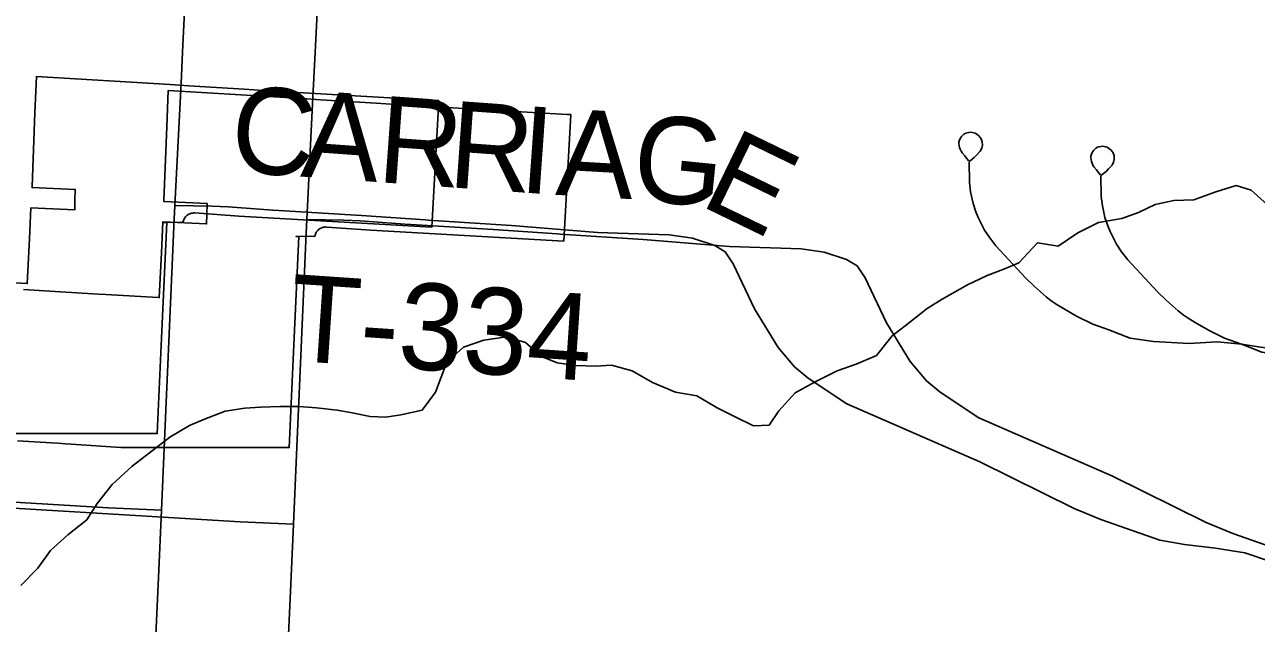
# Model space of a CAD drawing. Extents: x -38.2 to 41.9, y -4 to 24.9.
# Drawn here: x 6.95 to 7.758, y 19.034 to 19.427 of the extents above; entities that cross this region are included whole.
import ezdxf

# ---------------------------------------------------------------- set-up
doc = ezdxf.new("R2010")
doc.units = 0
for name, color, linetype in [('Default', 7, 'Continuous'), ('GM_X_County_Road', 7, 'Continuous'), ('GM_X_Minor_River', 7, 'Continuous'), ('GM_X_State_Location', 7, 'Continuous'), ('GM_X_Township_Road', 7, 'Continuous'), ('GM_X_Township_Road_Text', 7, 'Continuous')]:
    doc.layers.add(name, color=color, linetype=linetype)

msp = doc.modelspace()

# ---------------------------------------------------------------- linework, layer by layer
at = {"layer": 'Default'}
msp.add_lwpolyline([(6.9422, 19.15865), (6.95656, 19.15863), (6.97865, 19.15861), (7.03318, 19.15854), (7.03523, 19.15853), (7.03713, 19.15853), (7.04043, 19.23085), (7.04344, 19.29702), (7.04152, 19.2971), (7.05388, 19.29721), (7.05492, 19.29983), (7.05561, 19.30073), (7.05601, 19.30114), (7.05658, 19.30164), (7.05689, 19.30186), (7.05736, 19.30217), (7.05802, 19.30253), (7.05873, 19.30282), (7.05928, 19.30299), (7.05963, 19.30307), (7.06039, 19.3032), (7.06096, 19.30324), (7.06172, 19.30323), (7.09067, 19.30112), (7.21713, 19.29403), (7.22169, 19.37702), (7.21946, 19.37712), (7.10687, 19.38368), (7.09418, 19.38445), (7.05777, 19.38668), (7.04567, 19.38743), (6.95786, 19.39276), (6.95683, 19.36897), (6.95502, 19.3206), (6.95499, 19.31988), (6.98335, 19.31873), (6.98317, 19.31116), (6.98302, 19.30526), (6.95433, 19.30663), (6.95334, 19.28639), (6.95251, 19.26937), (6.9519, 19.25694), (6.95154, 19.25696), (6.93589, 19.25787)], dxfattribs=at)
at = {"layer": 'GM_X_County_Road'}
for points in [[(7.05271, 19.38845), (7.05397, 19.41352), (7.06396, 19.6125), (7.06434, 19.61953)], [(7.04831, 19.29914), (7.04871, 19.30822), (7.05271, 19.38845)], [(6.94556, 19.15388), (6.96776, 19.15244), (6.97191, 19.15217), (6.97698, 19.15184), (6.98068, 19.1516), (7.01319, 19.14948), (7.02867, 19.14946), (7.04304, 19.14945), (7.06513, 19.14942), (7.11966, 19.14935), (7.12171, 19.14934), (7.12361, 19.14934), (7.1269, 19.22166), (7.12992, 19.28783), (7.128, 19.28791), (7.14036, 19.28802), (7.1414, 19.29064), (7.14209, 19.29154), (7.14249, 19.29195), (7.14306, 19.29245), (7.14336, 19.29267), (7.14384, 19.29299), (7.1445, 19.29334), (7.14521, 19.29363), (7.14576, 19.2938), (7.14611, 19.29389), (7.14687, 19.29401), (7.14744, 19.29405), (7.14819, 19.29404), (7.17715, 19.29193), (7.3036, 19.28484), (7.30816, 19.36783), (7.30594, 19.36793), (7.19334, 19.37449), (7.18066, 19.37526), (7.14424, 19.37749), (7.13215, 19.37824), (7.04434, 19.38357), (7.0433, 19.35978), (7.0415, 19.31141), (7.04147, 19.31069), (7.06983, 19.30954), (7.06965, 19.30197), (7.0695, 19.29607), (7.04081, 19.29745), (7.03982, 19.2772), (7.03899, 19.26018), (7.03838, 19.24775), (7.03802, 19.24777), (7.02236, 19.24869), (7.00335, 19.24979), (6.99859, 19.25007), (6.98448, 19.25092), (6.96659, 19.25199), (6.94954, 19.25302)], [(7.03553, 19.00186), (7.03605, 19.02162), (7.03797, 19.06405), (7.03985, 19.10826), (7.04183, 19.15386), (7.04831, 19.29914)]]:
    msp.add_lwpolyline(points, dxfattribs=at)
at = {"layer": 'GM_X_Minor_River'}
for points in [[(7.76474, 19.30874), (7.75414, 19.31823), (7.7443, 19.32126), (7.73106, 19.31709), (7.71668, 19.31179), (7.70343, 19.31141), (7.69132, 19.30876), (7.68035, 19.30346), (7.66938, 19.29967), (7.65424, 19.29702), (7.64062, 19.2902), (7.62776, 19.28148), (7.61413, 19.28376), (7.60203, 19.27049), (7.59219, 19.26632), (7.58122, 19.26215), (7.56835, 19.25609), (7.5517, 19.24662), (7.54186, 19.24055), (7.52938, 19.2307), (7.51879, 19.22274), (7.50857, 19.20985), (7.49533, 19.20417), (7.48284, 19.19962), (7.46846, 19.19242), (7.45522, 19.18523), (7.44463, 19.17348), (7.4382, 19.164), (7.42798, 19.16362), (7.41549, 19.16969), (7.40413, 19.17538), (7.39088, 19.18335)], [(7.39088, 19.18335), (7.37688, 19.18563), (7.36174, 19.19208), (7.34849, 19.19966), (7.33486, 19.20346), (7.32465, 19.20271), (7.3114, 19.20309), (7.29929, 19.20499), (7.28907, 19.20916), (7.27847, 19.21826), (7.26598, 19.22206), (7.25122, 19.21979), (7.23798, 19.21525), (7.227, 19.20539), (7.21944, 19.18568), (7.21074, 19.17393), (7.19674, 19.1709), (7.1869, 19.16939), (7.17668, 19.16977), (7.16495, 19.17205), (7.15511, 19.17395), (7.14149, 19.17547), (7.13013, 19.17623), (7.11764, 19.17624), (7.10478, 19.17587), (7.09456, 19.17511), (7.08169, 19.17322), (7.06807, 19.16792), (7.05823, 19.16375), (7.04536, 19.15617), (7.03212, 19.14594), (7.02077, 19.13723), (7.00753, 19.1251), (6.99769, 19.11259), (6.99089, 19.10198), (6.9784, 19.09213), (6.96705, 19.0819), (6.95873, 19.07015), (6.94776, 19.05878)]]:
    msp.add_lwpolyline(points, dxfattribs=at)
at = {"layer": 'GM_X_State_Location'}
for points in [[(7.65532, 19.32834), (7.65291, 19.33155), (7.6512, 19.33348), (7.6505, 19.33462), (7.64992, 19.33582), (7.64949, 19.33708), (7.64907, 19.3397), (7.64913, 19.34047), (7.64971, 19.34251), (7.65083, 19.34432), (7.65242, 19.34573), (7.65358, 19.34636), (7.65459, 19.34673), (7.65671, 19.34702), (7.65883, 19.34671), (7.65983, 19.34633), (7.66077, 19.34583), (7.66242, 19.34448), (7.66367, 19.34274), (7.66439, 19.34074), (7.66452, 19.33861), (7.66405, 19.33652), (7.66301, 19.33465), (7.66078, 19.33211), (7.65919, 19.33053), (7.6575, 19.32905), (7.65578, 19.32774), (7.65599, 19.31404), (7.65673, 19.30787), (7.6584, 19.30022), (7.66018, 19.29485), (7.66176, 19.29102), (7.6659, 19.28278), (7.66931, 19.27765), (7.67339, 19.27255), (7.69285, 19.25155), (7.69852, 19.24609), (7.70631, 19.23913), (7.70969, 19.23645), (7.7129, 19.2343), (7.71758, 19.23131), (7.72627, 19.22629), (7.73686, 19.22119), (7.748, 19.21712), (7.7518, 19.21566)], [(7.13519, 19.29903), (7.1595, 19.29859), (7.17004, 19.29799), (7.19938, 19.2959), (7.20332, 19.29566)], [(7.20332, 19.29566), (7.25754, 19.29238), (7.29927, 19.28955), (7.30121, 19.28942)], [(7.30121, 19.28942), (7.35573, 19.28589), (7.41219, 19.28118), (7.45925, 19.27962), (7.47441, 19.27752), (7.48905, 19.27281), (7.49585, 19.26863), (7.50112, 19.26072), (7.51509, 19.23118), (7.53065, 19.20577), (7.54144, 19.19307), (7.55033, 19.18577), (7.57573, 19.16893), (7.66279, 19.13072), (7.72472, 19.10016), (7.74211, 19.09297), (7.76337, 19.08547)], [(7.7518, 19.21566), (7.7613, 19.212), (7.77659, 19.20973), (7.80002, 19.20842), (7.8184, 19.20957), (7.83466, 19.2081), (7.84686, 19.20598), (7.85874, 19.20468), (7.86985, 19.20194)], [(6.82464, 19.11619), (6.82563, 19.11613), (6.93937, 19.10974), (7.02288, 19.10473), (7.09154, 19.10063), (7.12633, 19.09907)]]:
    msp.add_lwpolyline(points, dxfattribs=at)
at = {"layer": 'GM_X_Township_Road'}
for points in [[(7.56884, 19.33753), (7.56643, 19.34074), (7.56472, 19.34267), (7.56402, 19.34381), (7.56345, 19.345), (7.56301, 19.34627), (7.56259, 19.34889), (7.56265, 19.34966), (7.56323, 19.3517), (7.56435, 19.3535), (7.56594, 19.35492), (7.56711, 19.35555), (7.56811, 19.35592), (7.57023, 19.35621), (7.57235, 19.3559), (7.57335, 19.35552), (7.5743, 19.35501), (7.57594, 19.35367), (7.57719, 19.35193), (7.57791, 19.34993), (7.57804, 19.34779), (7.57757, 19.34571), (7.57653, 19.34384), (7.5743, 19.34129), (7.57272, 19.33972), (7.57103, 19.33824), (7.5693, 19.33693), (7.56952, 19.32323), (7.57026, 19.31706), (7.57192, 19.30941), (7.5737, 19.30404), (7.57528, 19.30021), (7.57942, 19.29197), (7.58283, 19.28684), (7.58692, 19.28174), (7.60637, 19.26074), (7.61204, 19.25528), (7.61983, 19.24832), (7.62322, 19.24564), (7.62642, 19.24348), (7.63111, 19.2405), (7.63979, 19.23548), (7.65038, 19.23038), (7.66152, 19.22631), (7.66532, 19.22485)], [(7.04871, 19.30822), (7.07302, 19.30778), (7.08356, 19.30718), (7.1129, 19.30509), (7.11685, 19.30485)], [(7.11685, 19.30485), (7.17106, 19.30157), (7.21279, 19.29874), (7.21474, 19.29861)], [(7.21474, 19.29861), (7.26925, 19.29508), (7.32572, 19.29037), (7.37277, 19.28881), (7.38793, 19.28671), (7.40257, 19.282), (7.40937, 19.27782), (7.41464, 19.26991), (7.42862, 19.24037), (7.44417, 19.21496), (7.45496, 19.20226), (7.46385, 19.19496), (7.48925, 19.17812), (7.57631, 19.13991), (7.63824, 19.10935), (7.65563, 19.10215), (7.6769, 19.09465), (7.69444, 19.08853), (7.71052, 19.08582), (7.73089, 19.08333), (7.75012, 19.08038), (7.76755, 19.0745)], [(7.66532, 19.22485), (7.67482, 19.22119), (7.69011, 19.21892), (7.71354, 19.21761), (7.73192, 19.21875), (7.74818, 19.21729), (7.76038, 19.21517), (7.77226, 19.21387), (7.78337, 19.21113)], [(6.73816, 19.12538), (6.73915, 19.12532), (6.85289, 19.11893), (6.9364, 19.11392), (7.00506, 19.10982), (7.03985, 19.10826)]]:
    msp.add_lwpolyline(points, dxfattribs=at)
at = {"layer": 'GM_X_Township_Road_Text'}
for points in [[(7.13919, 19.37926), (7.14044, 19.40433), (7.15044, 19.60331), (7.15082, 19.61034)], [(7.13478, 19.28995), (7.13519, 19.29903), (7.13919, 19.37926)], [(7.12201, 18.99267), (7.12253, 19.01244), (7.12444, 19.05486), (7.12633, 19.09907), (7.12831, 19.14468), (7.13478, 19.28995)]]:
    msp.add_lwpolyline(points, dxfattribs=at)

# ---------------------------------------------------------------- texts
for s, height, rotation, p in [('C', 0.05682, 355.88672, (7.08409, 19.33052)), ('A', 0.05682, 355.89006, (7.13064, 19.32717)), ('R', 0.05682, 355.88672, (7.18051, 19.32359)), ('R', 0.05682, 355.89239, (7.22706, 19.32024)), ('I', 0.05682, 355.93977, (7.27366, 19.31689)), ('A', 0.05682, 356.71045, (7.29777, 19.31519)), ('G', 0.05682, 354.2055, (7.34703, 19.31237)), ('E', 0.05682, 334.13166, (7.39174, 19.30875)), ('T-334', 0.056818, 356.11213, (7.12235, 19.20651))]:
    msp.add_text(s, height=height, rotation=rotation, dxfattribs=at).set_placement(p)

doc.saveas('drawing.dxf')
